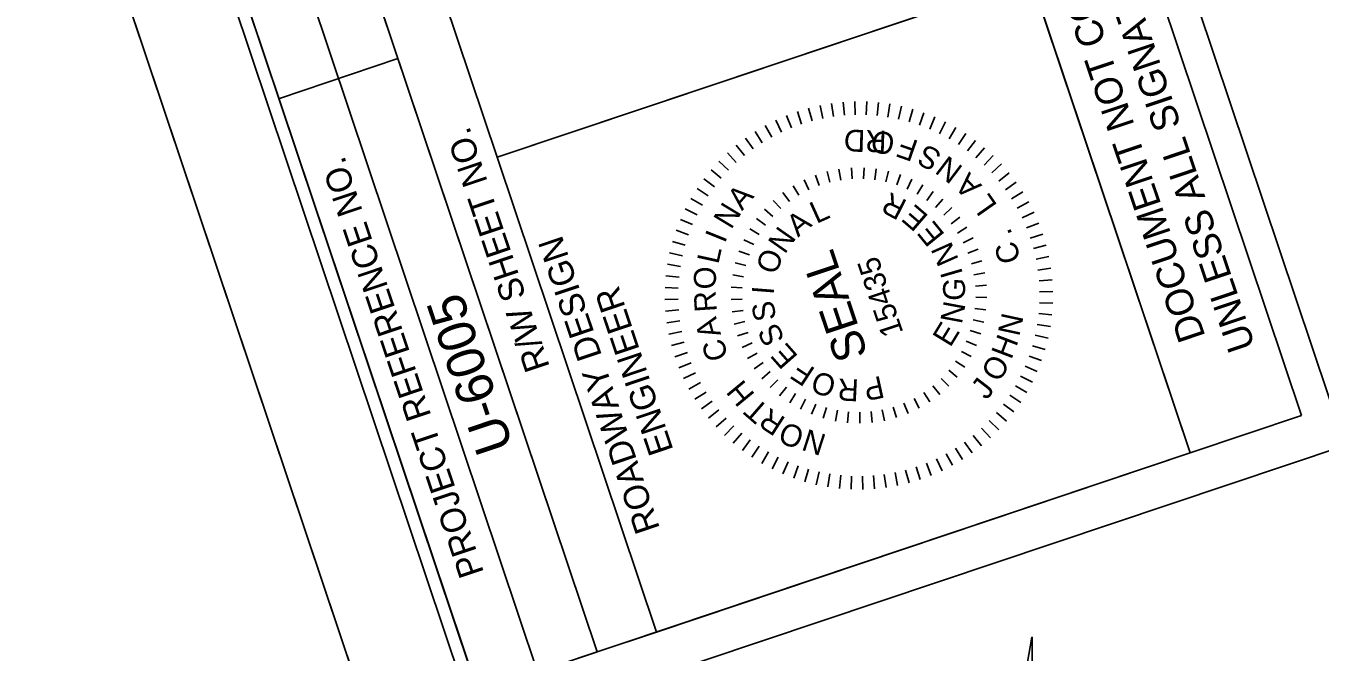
# Model space of a CAD drawing. Extents: x 1615436 to 1617010, y 903110 to 905055.
# Drawn here: x 1615436.4 to 1615695, y 904515.9 to 904641 of the extents above; entities that cross this region are included whole.
import ezdxf

# ---------------------------------------------------------------- set-up
doc = ezdxf.new("R2010")
doc.units = 0
for name, color, linetype in [('Exist Plan Preparation Drainage Flow Arrows', 7, 'Continuous'), ('Exist Plan Preparation Drainage Notes Label', 7, 'Continuous'), ('Exist Plan Preparation Watershed Blue', 7, 'Continuous'), ('Exist Structure Minor Pipes CMP 15 Inch Text', 7, 'Continuous'), ('Exist Structure Minor Pipes CMP 24 Inch Text', 7, 'Continuous'), ('Prop Drainage Structure Catch Basin Grate 840 03E CELL', 7, 'Continuous'), ('Prop Plan Preparation Sag Label', 7, 'Continuous'), ('Scratch_Level_7', 7, 'Continuous'), ('Scratch_Level_8', 7, 'Continuous')]:
    doc.layers.add(name, color=color, linetype=linetype)

msp = doc.modelspace()

# ---------------------------------------------------------------- linework, layer by layer
at = {"layer": 'Exist Plan Preparation Drainage Flow Arrows'}
msp.add_lwpolyline([(1616986.86, 903464.68), (1616457.04, 905044.17), (1615456.82, 904708.68), (1615986.63, 903129.17)], close=True, dxfattribs=at)
at = {"layer": 'Exist Plan Preparation Drainage Notes Label'}
msp.add_lwpolyline([(1617009.96, 903458.71), (1616474.57, 905054.81), (1615436.42, 904706.58), (1615971.81, 903110.48)], close=True, dxfattribs=at)
at = {"layer": 'Exist Plan Preparation Watershed Blue'}
for p, q in [((1615595.09, 904625.12), (1615595.62, 904622.53)), ((1615597.4, 904625.52), (1615597.77, 904622.91)), ((1615599.72, 904625.78), (1615599.94, 904623.15)), ((1615602.06, 904625.9), (1615602.12, 904623.25)), ((1615604.4, 904625.87), (1615604.29, 904623.23)), ((1615606.74, 904625.7), (1615606.47, 904623.08)), ((1615609.06, 904625.4), (1615608.63, 904622.79)), ((1615588.37, 904623.1), (1615589.36, 904620.65)), ((1615590.57, 904623.91), (1615591.41, 904621.4)), ((1615592.81, 904624.58), (1615593.5, 904622.03)), ((1615611.36, 904624.96), (1615610.77, 904622.38)), ((1615613.62, 904624.37), (1615612.89, 904621.84)), ((1615615.85, 904623.66), (1615614.96, 904621.17)), ((1615618.03, 904622.8), (1615617, 904620.37)), ((1615582.13, 904619.91), (1615583.54, 904617.67)), ((1615584.15, 904621.1), (1615585.42, 904618.78)), ((1615586.23, 904622.16), (1615587.36, 904619.78)), ((1615620.16, 904621.82), (1615618.98, 904619.46)), ((1615622.22, 904620.71), (1615620.9, 904618.43)), ((1615580.19, 904618.6), (1615581.73, 904616.45)), ((1615624.21, 904619.48), (1615622.75, 904617.28)), ((1615626.12, 904618.13), (1615624.54, 904616.02)), ((1615576.57, 904615.63), (1615578.36, 904613.69)), ((1615578.33, 904617.17), (1615580.01, 904615.12)), ((1615627.95, 904616.67), (1615626.24, 904614.66)), ((1615629.69, 904615.1), (1615627.86, 904613.19)), ((1615573.32, 904612.26), (1615575.34, 904610.55)), ((1615574.89, 904614), (1615576.8, 904612.17)), ((1615599.21, 904610.21), (1615598.87, 904612.38)), ((1615601.4, 904612.65), (1615601.53, 904610.46)), ((1615603.87, 904612.67), (1615603.78, 904610.47)), ((1615606.33, 904612.45), (1615606.03, 904610.27)), ((1615631.32, 904613.43), (1615629.38, 904611.64)), ((1615571.86, 904610.43), (1615573.97, 904608.85)), ((1615591.89, 904610.23), (1615592.83, 904608.24)), ((1615594.17, 904611.18), (1615594.92, 904609.11)), ((1615596.53, 904611.9), (1615597.07, 904609.77)), ((1615608.75, 904612), (1615608.25, 904609.86)), ((1615611.13, 904611.31), (1615610.41, 904609.23)), ((1615613.42, 904610.4), (1615612.51, 904608.4)), ((1615632.86, 904611.66), (1615630.81, 904609.99)), ((1615634.29, 904609.81), (1615632.14, 904608.26)), ((1615570.51, 904608.52), (1615572.72, 904607.06)), ((1615587.67, 904607.69), (1615588.97, 904605.92)), ((1615589.72, 904609.06), (1615590.85, 904607.17)), ((1615615.61, 904609.27), (1615614.51, 904607.36)), ((1615617.69, 904607.93), (1615616.41, 904606.14)), ((1615635.6, 904607.86), (1615633.36, 904606.45)), ((1615568.17, 904604.46), (1615570.54, 904603.28)), ((1615569.28, 904606.53), (1615571.57, 904605.21)), ((1615584, 904604.39), (1615585.63, 904602.91)), ((1615585.75, 904606.13), (1615587.22, 904604.5)), ((1615619.62, 904606.41), (1615618.18, 904604.74)), ((1615621.4, 904604.69), (1615619.8, 904603.18)), ((1615636.79, 904605.85), (1615634.47, 904604.58)), ((1615567.19, 904602.34), (1615569.62, 904601.3)), ((1615582.42, 904602.49), (1615584.19, 904601.17)), ((1615623.01, 904602.82), (1615621.27, 904601.47)), ((1615637.85, 904603.76), (1615635.47, 904602.63)), ((1615566.34, 904600.16), (1615568.83, 904599.27)), ((1615581.04, 904600.45), (1615582.92, 904599.31)), ((1615624.43, 904600.8), (1615622.57, 904599.62)), ((1615638.79, 904601.62), (1615636.34, 904600.64)), ((1615639.6, 904599.42), (1615637.09, 904598.59)), ((1615565.62, 904597.93), (1615568.16, 904597.2)), ((1615579.86, 904598.28), (1615581.84, 904597.32)), ((1615625.65, 904598.65), (1615623.68, 904597.66)), ((1615640.27, 904597.18), (1615637.72, 904596.5)), ((1615565.04, 904595.67), (1615567.61, 904595.08)), ((1615578.89, 904596.02), (1615580.96, 904595.25)), ((1615626.65, 904596.4), (1615624.6, 904595.61)), ((1615627.43, 904594.06), (1615625.31, 904593.46)), ((1615640.81, 904594.9), (1615638.23, 904594.37)), ((1615564.59, 904593.37), (1615567.2, 904592.94)), ((1615578.14, 904593.66), (1615580.28, 904593.1)), ((1615627.98, 904591.66), (1615625.82, 904591.27)), ((1615641.21, 904592.6), (1615638.6, 904592.23)), ((1615564.29, 904591.04), (1615566.91, 904590.78)), ((1615577.63, 904591.25), (1615579.8, 904590.9)), ((1615626.11, 904589.02), (1615628.31, 904589.19)), ((1615641.47, 904590.27), (1615638.84, 904590.06)), ((1615564.1, 904586.37), (1615566.74, 904586.43)), ((1615564.12, 904588.71), (1615566.76, 904588.6)), ((1615577.31, 904586.33), (1615579.52, 904586.4)), ((1615577.35, 904588.8), (1615579.55, 904588.65)), ((1615628.38, 904586.74), (1615626.18, 904586.78)), ((1615641.59, 904587.93), (1615638.94, 904587.88)), ((1615564.22, 904584.03), (1615566.85, 904584.25)), ((1615577.51, 904583.87), (1615579.7, 904584.15)), ((1615628.22, 904584.28), (1615626.03, 904584.53)), ((1615641.57, 904585.59), (1615638.92, 904585.7)), ((1615564.47, 904581.7), (1615567.09, 904582.08)), ((1615577.95, 904581.44), (1615580.09, 904581.93)), ((1615627.83, 904581.84), (1615625.67, 904582.3)), ((1615641.1, 904580.94), (1615638.49, 904581.36)), ((1615641.4, 904583.26), (1615638.77, 904583.52)), ((1615564.88, 904579.4), (1615567.46, 904579.93)), ((1615578.62, 904579.06), (1615580.7, 904579.76)), ((1615580.7, 904579.76), (1615578.62, 904579.06)), ((1615627.2, 904579.45), (1615625.1, 904580.12)), ((1615640.65, 904578.64), (1615638.07, 904579.22)), ((1615565.41, 904577.12), (1615567.96, 904577.81)), ((1615579.51, 904576.76), (1615581.52, 904577.66)), ((1615625.26, 904574.92), (1615623.33, 904575.97)), ((1615626.34, 904577.14), (1615624.31, 904578)), ((1615640.07, 904576.37), (1615637.53, 904577.11)), ((1615566.09, 904574.88), (1615568.59, 904575.72)), ((1615566.89, 904572.68), (1615569.34, 904573.66)), ((1615580.62, 904574.56), (1615582.54, 904575.64)), ((1615581.94, 904572.47), (1615583.74, 904573.74)), ((1615623.98, 904572.81), (1615622.16, 904574.05)), ((1615639.35, 904574.15), (1615636.86, 904575.03)), ((1615567.83, 904570.54), (1615570.22, 904571.67)), ((1615583.45, 904570.52), (1615585.13, 904571.96)), ((1615622.5, 904570.84), (1615620.8, 904572.25)), ((1615637.51, 904569.84), (1615635.15, 904571.02)), ((1615638.49, 904571.96), (1615636.07, 904573)), ((1615568.9, 904568.45), (1615571.21, 904569.73)), ((1615585.15, 904568.73), (1615586.68, 904570.32)), ((1615587.01, 904567.11), (1615588.38, 904568.84)), ((1615619, 904567.37), (1615617.61, 904569.07)), ((1615620.83, 904569.02), (1615619.28, 904570.58)), ((1615636.4, 904567.78), (1615634.12, 904569.1)), ((1615570.09, 904566.44), (1615572.32, 904567.85)), ((1615571.4, 904564.5), (1615573.55, 904566.04)), ((1615589.02, 904565.67), (1615590.21, 904567.53)), ((1615591.16, 904564.44), (1615592.17, 904566.4)), ((1615612.67, 904563.57), (1615611.82, 904565.6)), ((1615614.89, 904564.63), (1615613.86, 904566.57)), ((1615617.01, 904565.9), (1615615.79, 904567.73)), ((1615635.17, 904565.78), (1615632.97, 904567.24)), ((1615572.82, 904562.64), (1615574.87, 904564.31)), ((1615593.4, 904563.42), (1615594.22, 904565.46)), ((1615595.74, 904562.62), (1615596.35, 904564.73)), ((1615598.14, 904562.05), (1615598.55, 904564.21)), ((1615600.58, 904561.71), (1615600.78, 904563.9)), ((1615603.05, 904561.61), (1615603.03, 904563.81)), ((1615605.51, 904561.75), (1615605.28, 904563.94)), ((1615607.95, 904562.13), (1615607.51, 904564.28)), ((1615610.34, 904562.74), (1615609.7, 904564.84)), ((1615632.36, 904562.04), (1615630.35, 904563.75)), ((1615633.82, 904563.87), (1615631.71, 904565.46)), ((1615574.36, 904560.88), (1615576.3, 904562.66)), ((1615576, 904559.2), (1615577.83, 904561.11)), ((1615629.12, 904558.67), (1615627.33, 904560.61)), ((1615630.79, 904560.31), (1615628.89, 904562.14)), ((1615577.74, 904557.63), (1615579.45, 904559.64)), ((1615579.56, 904556.17), (1615581.15, 904558.28)), ((1615625.5, 904555.71), (1615623.95, 904557.86)), ((1615627.35, 904557.13), (1615625.68, 904559.18)), ((1615581.48, 904554.82), (1615582.93, 904557.02)), ((1615583.47, 904553.59), (1615584.79, 904555.88)), ((1615621.54, 904553.21), (1615620.27, 904555.52)), ((1615623.55, 904554.4), (1615622.15, 904556.63)), ((1615585.53, 904552.48), (1615586.71, 904554.84)), ((1615587.65, 904551.5), (1615588.69, 904553.93)), ((1615589.84, 904550.65), (1615590.72, 904553.13)), ((1615615.12, 904550.39), (1615614.28, 904552.9)), ((1615617.31, 904551.2), (1615616.33, 904553.65)), ((1615619.46, 904552.14), (1615618.33, 904554.53)), ((1615592.06, 904549.93), (1615592.8, 904552.46)), ((1615594.33, 904549.34), (1615594.91, 904551.92)), ((1615596.63, 904548.9), (1615597.05, 904551.51)), ((1615598.95, 904548.6), (1615599.21, 904551.22)), ((1615601.28, 904548.43), (1615601.39, 904551.07)), ((1615603.62, 904548.4), (1615603.57, 904551.05)), ((1615605.96, 904548.52), (1615605.75, 904551.16)), ((1615608.29, 904548.78), (1615607.92, 904551.4)), ((1615610.59, 904549.18), (1615610.07, 904551.77)), ((1615612.87, 904549.72), (1615612.19, 904552.27))]:
    msp.add_line(p, q, dxfattribs=at)
at = {"layer": 'Exist Structure Minor Pipes CMP 15 Inch Text'}
for p, q in [((1615627.69, 904752.81), (1615691.3, 904563.16)), ((1615627.69, 904752.81), (1615691.3, 904563.16)), ((1615669.02, 904555.68), (1615605.41, 904745.34)), ((1615669.02, 904555.68), (1615605.41, 904745.34)), ((1615691.3, 904563.16), (1615669.02, 904555.68)), ((1615691.3, 904563.16), (1615669.02, 904555.68))]:
    msp.add_line(p, q, dxfattribs=at)
at = {"layer": 'Exist Structure Minor Pipes CMP 24 Inch Text'}
msp.add_line((1615436.42, 904706.58), (1615971.81, 903110.48), dxfattribs=at)
at = {"layer": 'Prop Drainage Structure Catch Basin Grate 840 03E CELL'}
msp.add_lwpolyline([(1616672.58, 903656.2), (1616919.77, 903656.8), (1616590.65, 904611.24), (1616386.84, 904624.44), (1616334.81, 904821.64), (1616466, 905009.57), (1615641.09, 904732.87), (1615700.02, 904557.19), (1615560.35, 904510.33), (1615954.19, 903336.21)], close=True, dxfattribs=at)
at = {"layer": 'Prop Plan Preparation Sag Label'}
for p, q in [((1615629.23, 904472.53), (1615637.43, 904518.88)), ((1615637.48, 904518.88), (1615637.43, 904518.88)), ((1615637.48, 904518.88), (1615637.43, 904518.88)), ((1615637.48, 904518.88), (1615637.48, 904471.08))]:
    msp.add_line(p, q, dxfattribs=at)
at = {"layer": 'Scratch_Level_8'}
for p, q in [((1615550.54, 904515.93), (1615486.9, 904705.57)), ((1615550.54, 904515.93), (1615486.9, 904705.57)), ((1615538.66, 904511.93), (1615475.05, 904701.6)), ((1615530.56, 904614.75), (1615637.18, 904650.53)), ((1615487.07, 904626.5), (1615510.76, 904634.49)), ((1615550.54, 904515.93), (1615562.38, 904519.9))]:
    msp.add_line(p, q, dxfattribs=at)
for points in [[(1615463.14, 904697.64), (1615940.18, 903275.48), (1616935.67, 903609.4), (1616458.64, 905031.54)], [(1616935.67, 903609.4), (1615940.21, 903275.46), (1615526.76, 904507.95), (1615669.02, 904555.68), (1615605.42, 904745.34), (1616458.64, 905031.54)], [(1615530.56, 904614.75), (1615498.75, 904709.55), (1615605.42, 904745.34), (1615637.23, 904650.54)], [(1615526.76, 904507.95), (1615463.14, 904697.64), (1615486.9, 904705.57), (1615550.54, 904515.93)], [(1615562.38, 904519.9), (1615530.56, 904614.75), (1615637.23, 904650.54), (1615669.02, 904555.68)]]:
    msp.add_lwpolyline(points, close=True, dxfattribs=at)

# ---------------------------------------------------------------- texts
at = {"layer": 'Exist Plan Preparation Watershed Blue'}
for s, height, rotation, p in [(' RD', 4.399, 178.1358, (1615610.06, 904620)), ('O ', 4.399, 169.463, (1615610.28, 904619.4)), ('F', 4.4, 160.6704, (1615614.96, 904617.94)), ('S', 4.4, 151.7878, (1615619.66, 904615.65)), ('N', 4.4, 142.9051, (1615623.86, 904612.71)), ('A', 4.4, 134.0825, (1615627.58, 904609.13)), ('A', 4.4, 48.9804, (1615579.49, 904603.96)), ('R', 4.4, 153.0282, (1615612.72, 904605.98)), ('L', 4.4, 125.08, (1615630.62, 904605.13)), ('N', 4.4, 58.748, (1615577.33, 904600.18)), ('L', 4.4, 24.334, (1615594.36, 904601.41)), ('E', 4.4, 139.2571, (1615616.95, 904602.98)), ('A', 4.4, 39.6302, (1615590.68, 904598.68)), ('E', 4.4, 129.2713, (1615620.16, 904599.29)), ('I', 4.4, 68.0424, (1615576.06, 904597.43)), ('N', 4.4, 54.9265, (1615588.03, 904595.25)), ('.', 4.4, 112.2956, (1615633.57, 904599.37)), ('N', 4.4, 113.8792, (1615622.86, 904594.32)), ('C', 4.4, 104.5533, (1615635.19, 904594.15)), ('L', 4.4, 77.6179, (1615574.76, 904593.26)), ('O', 4.4, 70.2227, (1615586.31, 904591.11)), ('SEAL', 6.603, 108.4633, (1615604.71, 904575.3)), ('15435', 4.399, 108.4633, (1615611.76, 904579.74)), ('O', 4.4, 90.7542, (1615574.32, 904588.39)), ('I', 4.4, 106.2495, (1615623.67, 904591.44)), ('G', 4.4, 88.1547, (1615623.99, 904586.02)), ('R', 4.4, 93.811, (1615574.47, 904583.95)), ('I', 4.4, 85.519, (1615585.81, 904587.2)), ('S', 4.4, 100.8152, (1615586.39, 904582.46)), ('N', 4.4, 79.3885, (1615623.4, 904581.29)), ('A', 4.4, 105.8203, (1615575.33, 904579.32)), ('S', 4.4, 116.1115, (1615588.13, 904578.41)), ('E', 4.4, 58.5334, (1615621.09, 904576.62)), ('N', 4.4, 77.7855, (1615634.87, 904578.83)), ('H', 4.4, 69.1129, (1615633.29, 904574.19)), ('C', 4.4, 105.8203, (1615576.77, 904574.73)), ('E', 4.4, 131.4077, (1615590.87, 904574.97)), ('O', 4.4, 60.4702, (1615630.91, 904569.61)), ('F', 4.4, 146.7039, (1615594.34, 904572.42)), ('O', 4.4, 162.0002, (1615598.64, 904570.77)), ('P', 4.4, 192.5927, (1615607.28, 904571.12)), ('J', 4.4, 52.3983, (1615628.38, 904566.12)), ('H', 4.4, 129.531, (1615582.22, 904567.33)), ('R', 4.4, 177.2964, (1615602.93, 904570.37)), ('T', 4.4, 138.9629, (1615585.16, 904564.57)), ('R', 4.4, 147.1239, (1615588.43, 904562.55)), ('O', 4.4, 160.1806, (1615592.25, 904560.46)), ('N', 4.4, 162.1401, (1615596.57, 904559.24))]:
    msp.add_text(s, height=height, rotation=rotation, dxfattribs=at).set_placement(p)
at = {"layer": 'Exist Structure Minor Pipes CMP 15 Inch Text'}
for s, p in [('UNLESS ALL SIGNATURES COMPLETED', (1615682.09, 904576.94)), ('UNLESS ALL SIGNATURES COMPLETED', (1615682.09, 904576.94)), ('DOCUMENT NOT CONSIDERED FINAL', (1615672.13, 904578.95)), ('DOCUMENT NOT CONSIDERED FINAL', (1615672.13, 904578.95))]:
    msp.add_text(s, height=5.5, rotation=108.5432, dxfattribs=at).set_placement(p)
at = {"layer": 'Scratch_Level_7'}
msp.add_text('U-6005', height=7.5, rotation=108.5432, dxfattribs=at).set_placement((1615533.87, 904556.94))
at = {"layer": 'Scratch_Level_8'}
for s, height, p in [('R/W SHEET NO.', 5.0001, (1615541.13, 904572.89)), ('PROJECT REFERENCE NO.', 5.0001, (1615527.97, 904531.77)), ('ROADWAY DESIGN', 5.0001, (1615563.14, 904540.59)), ('ENGINEER', 5, (1615565.84, 904556.25))]:
    msp.add_text(s, height=height, rotation=108.5432, dxfattribs=at).set_placement(p)

doc.saveas('drawing.dxf')
